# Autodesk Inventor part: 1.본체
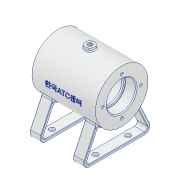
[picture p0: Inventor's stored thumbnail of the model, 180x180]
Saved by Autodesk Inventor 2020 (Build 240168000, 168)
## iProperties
Created: 2021-12
Part Number: 1.본체
Material: 알루미늄 6061
Document SubType Name: Modeling
Designer: Administrator
Mass: 310.271 g
Surface Area: 354.961 cm^2
Volume: 114.915 cm^3
Density: 2.7 g/cm^3
Appearance: 알루미늄 - 평지
Author: Administrator
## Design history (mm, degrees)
sketch "스케치1"
  geometry: L1 (-35, 0)-(35, 0); L2 (-35, 0)-(-35, 29); L3 (-35, 29)-(35, 29); L4 (35, 29)-(35, 0); L5 (-35, 16)-(-23, 16); L6 (-23, 16)-(-23, 14); L7 (-23, 14)-(-21, 14); L8 (-21, 14)-(-21, 21); L9 (-21, 21)-(21, 21); L10 (21, 21)-(21, 14); L11 (21, 14)-(23, 14); L12 (23, 14)-(23, 16); L13 (23, 16)-(35, 16); 1 further point
  constraints: 26 end point, 8 perpendicular, 6 point on line, 2 horizontal, 1 midpoint, 1 vertical
  dimensions: "d0" = 70 distance of L1.start L1.end; "d1" = 35 distance of point (0, 0) L1.start; "d2" = 58 diameter of L3 L1; "d3" = 28 diameter of L11 L1; "d4" = 32 diameter of L13 L1; "d5" = 42 diameter of L9 L1; "d6" = 12 distance between parallel lines of L4 L12; "d7" = 2 distance from line of L11.end L10; "d8" = 42 distance between parallel lines of L8 L10; "d9" = 12 distance between parallel lines of L2 L6
revolve "회전1" sketch "스케치1" stored, may be unused: angle "d10" = 90 deg
node "작업 평면1"
sketch "스케치2"
  geometry: L1 (-17.993, 22.743)-(-55, 40); L2 (-55, 40)-(-55, -40); L3 (-55, -40)-(-17.993, -22.743); A1 r 29 centre (0, 0) between (-17.993, 22.743) and (-17.993, -22.743) reference; 2 further points
  constraints: 6 end point, 2 point on circle, 1 horizontal alignment, 1 midpoint, 1 vertical
  dimensions: "d12" = 65 deg angle of L2 L3; "d13" = 65 deg angle of L2 L1; "d14" = 80 distance of L1.end L2.end; "d15" = 55 distance from line of L2 point (0, 0)
extrude "돌출1" join sketch "스케치2" distance "d16" = 12; taper "d17" = 0 deg
sketch "스케치4"
  geometry: L1 (40, -55)-(22.743, -17.993) reference; L2 (-40, -55)-(40, -55) reference; L3 (-22.743, -17.993)-(-40, -55) reference; L4 (20.574, -20.438)-(35.291, -52); L5 (35.291, -52)-(-35.291, -52); L6 (-35.291, -52)-(-20.574, -20.438); A1 r 29 centre (0, 0) between (-22.743, -17.993) and (22.743, -17.993) reference; 1 further point
  constraints: 6 end point, 2 point on circle, 1 equal length
  dimensions: "d18" = 3 distance between parallel lines of L1 L4; "d19" = 65 deg angle of L5 L6; "d20" = 65 deg angle of L5 L4; "d21" = 52 distance from line of L5 point (0, 0)
extrude "돌출2" cut sketch "스케치4" distance "d22" = 12; taper "d23" = 0 deg
fillet "모깎기1" dims "d24" = 6
fillet "모깎기2" dims "d25" = 3
fillet "모깎기3" dims "d26" = 0.5
fillet "모깎기4" dims "d27" = 3
sketch "스케치5"
  geometry: L1 (11.5, 66.664)-(11.5, 61.164) reference; C1 r 3 at (5.5, 48.582); C2 r 3 at (5.5, 12.582); 2 further points
  constraints: 2 centre point, 1 vertical alignment
  dimensions: "d28" = 6 diameter of C1; "d29" = 6 distance from line of C1.centre L1; "d30" = 18 vertical distance of point (-18.5, 30.582) C1.centre; "d31" = 6 diameter of C2; "d32" = 36 distance of C2.centre C1.centre
hole "구멍1" sketch "스케치5" at (5.5, 48.582), (5.5, 12.582) diameter "d33" = 6; stored, may be unused: countersink angle "d37" = 90 deg, drill point angle "d39" = 118 deg; dims "d34" = 6, "d35" = 10, "d36" = 5.5, "d38" = 8
sketch "스케치6"
  geometry: L1 (0, 0)-(-30.07, -10.945); L2 (0, 0)-(-29, 0); 1 further point
  constraints: 4 end point, 1 horizontal, 1 horizontal alignment, 1 other
  dimensions: "d40" = 32 distance of L1.start L1.end; "d41" = 20 deg angle of L2 L1
node "작업 평면2"
sketch "스케치7"
  geometry: C1 r 6 at (0, 0); 1 further point
  constraints: 1 centre point, 1 coincident
  dimensions: "d42" = 12 diameter of C1
extrude "돌출3" join sketch "스케치7" stored distance "d43" = 12; taper "d44" = 0 deg
sketch "스케치8"
  geometry: C1 r 6 at (0, 0) reference; 2 further points
  constraints: 1 coincident
hole "구멍2" sketch "스케치8" at (0, 0) diameter "d45" = 5.1881; stored, may be unused: countersink angle "d49" = 90 deg, drill point angle "d51" = 0 deg; dims "d46" = 12, "d47" = 10, "d48" = 5.5, "d50" = 16
fillet "모깎기5" dims "d52" = 1
sketch "스케치9"
  geometry: C1 r 21 at (0, 0); C2 r 2 at (0, 21); 2 further points
  constraints: 2 centre point, 2 vertical alignment, 1 coincident, 1 other
  dimensions: "d53" = 42 diameter of C1; "d54" = 4 diameter of C2
hole "구멍3" sketch "스케치9" at (0, 21) diameter "d55" = 3.242; stored, may be unused: countersink angle "d59" = 90 deg, drill point angle "d61" = 118 deg; dims "d56" = 8, "d57" = 10, "d58" = 5.5, "d60" = 10
node "작업 평면3"
sketch "스케치10"
  geometry: C1 r 5 at (0, 0); 1 further point
  constraints: 1 centre point, 1 coincident
  dimensions: "d66" = 10 diameter of C1
extrude "돌출4" join sketch "스케치10" stored distance "d67" = 10; taper "d68" = 0 deg
fillet "모깎기6" dims "d83" = 1
fillet "모깎기7" dims "d84" = 0.3
fillet "모깎기8" dims "d85" = 3
chamfer "모따기1" distance "d86" = 1; stored, may be unused: second distance "d87" = 2, angle "d88" = 45 deg
sketch "스케치13"
  geometry: C1 r 5 at (0, 0) reference; 2 further points
  constraints: 1 coincident
hole "구멍6" sketch "스케치13" at (0, 0) diameter "d89" = 5.1881; stored, may be unused: countersink angle "d93" = 90 deg, drill point angle "d95" = 0 deg; dims "d90" = 12, "d91" = 6, "d92" = 2, "d94" = 6
sketch "스케치14"
  geometry: 1 further point
hole "구멍7" sketch "스케치14" at (0, 0) diameter "d96" = 3; stored, may be unused: countersink angle "d100" = 90 deg, drill point angle "d102" = 0 deg; dims "d97" = 12, "d98" = 5.2, "d99" = 2, "d101" = 6
chamfer "모따기2" distance "d103" = 0.5; stored, may be unused: second distance "d104" = 2, angle "d105" = 45 deg
node "작업 평면4"
sketch "스케치15"
  geometry: L1 (-35, -29)-(-35, 29) reference; L2 (-35, 29)-(35, 29) reference; 2 further points
  constraints: 1 other
  dimensions: "d106" = 35 distance from line of L1 point (0, 0); "d107" = 29 distance from line of L2 point (0, 0)
feature "엠보싱1" sketch "스케치15" dims "d0" = 70, "d12" = 65 deg, "d13" = 65 deg, "d14" = 80, "d15" = 55, "d108" = 0.5, "d109" = 0
node "솔리드1"
mirror "미러1"
mirror "미러2"
pattern_circular "원형 패턴1" dims angle "d63" = 360 deg
mirror "미러3"
feature "A9D066F2-1C7D-4E18-AEED-F7BC21143FA4" dims "d33" = 6, "d34" = 6, "d35" = 10, "d36" = 5.5, "d37" = 90 deg, "d38" = 8, "d39" = 118 deg
other parameters: "d65" = 32
